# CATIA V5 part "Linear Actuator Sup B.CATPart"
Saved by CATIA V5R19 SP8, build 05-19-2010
Part number: Linear Actuator Sup B
Bounding box of the stored display mesh (mm): x -24.865 to 24.865, y 132.679 to 469.81, z 725.003 to 774.997
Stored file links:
  G:\EU_thinkMotion\CFAO_2010\MMS_groupe3\MMS_groupe3\A reprendre\fovide\fovide\Linear Actuator Sup B.CATPart
  G:\EU_thinkMotion\CFAO_2010\MMS_groupe3\MMS_groupe3\A reprendre\fovide\fovide\fovide.CATProduct
  G:\EU_thinkMotion\CFAO_2010\MMS_groupe3\MMS_groupe3\A reprendre\fovide\fovide\Linear Actuator Sup A 9.CATPart
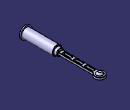
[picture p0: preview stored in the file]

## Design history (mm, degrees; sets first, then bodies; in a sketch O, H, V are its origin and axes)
Parameters
  `longueur poches` = 35 mm
External parameters (linked from other documents)
  `External.Rayon Linear Actuator Sup A` = 30 mm
  `External.Diamètre Linear Actuator Sup A` = 60 mm
Set1
  Plane1: linked copy from another document
  Point1 "Point.B": linked copy from another document
  Line1: linked copy from another document
  Plane2: linked copy from another document
  Line2: linked copy from another document
  DatumCurve1 to DatumCurve3: linked copy from another document
Body1 (main body)
  Sketch1 on Plane1, origin (0, 0, 750), H (1, 0, 0), V (0, 1, 0)
    arc A1 centre (0, 450) radius 20 from (-10, 432.6795) to (10, 432.6795) cw
    point P1 (0, 450)
    point P2 (-10, 432.6795)
    point P3 (10, 432.6795)
    reference projected point E1 (0, 450) from Point1
    point P4 (-10, 432.6795)
    line L1 (10, 432.6795) -> (10, 282.6795)
    line L2 (10, 282.6795) -> (-10, 282.6795)
    line L3 (-10, 282.6795) -> (-10, 432.6795)
    point P5 (10, 432.6795)
    radius A1 = 20
    length L1 = 150
    length L2 = 20 {= `External.Rayon Linear Actuator Sup A` *2/3}
    coincidence: P1 E1, P5 P3, P4 P2
    horizontal: L2 H
    vertical: L1 V, L3 V
  Pad1: profile Sketch1, direction (0, 0, 1), length 5 {= `External.Rayon Linear Actuator Sup A` /6}, mirrored extent
  Sketch2 on Plane2, origin (0, 0, 0), H (0, 1, 0), V (0, 0, 1)
    line L1 (282.6795, 750) -> (282.6795, 765)
    line L2 (282.6795, 765) -> (267.6795, 765)
    line L3 (267.6795, 765) -> (267.6795, 770)
    line L4 (267.6795, 770) -> (137.6795, 770)
    line L5 (137.6795, 770) -> (137.6795, 775)
    line L6 (137.6795, 775) -> (132.6795, 775)
    line L7 (132.6795, 775) -> (132.6795, 750)
    line L8 (132.6795, 750) -> (282.6795, 750)
    reference projected line E1 (282.6795, 745) -> (282.6795, 755) from edge [face of Pad1 from Sketch1.L1 | face of Pad1 from Sketch1.L2]
    reference projected line E2 (450, 750) -> (0, 750) from Line2
    length L6 = 5 {= `External.Rayon Linear Actuator Sup A` /6}
    length L5 = 5 {= `External.Rayon Linear Actuator Sup A` /6}
    length L1 = 15 {= `External.Rayon Linear Actuator Sup A` /2}
    length L2 = 15 {= `External.Rayon Linear Actuator Sup A` /2}
    length L7 = 25 {= `External.Rayon Linear Actuator Sup A` *5/6}
    length L4 = 130
    vertical: L1 V, L3 V, L5 V, L7 V
    horizontal: L2 H, L4 H, L6 H, L8 H
    coincidence: L1 E1, L8 E2
  Shaft1: profile Sketch2, axis Line2, angle 360
  Sketch3 on end face of Pad1, origin (0, 0, 755), H (1, 0, 0), V (0, 1, 0)
    line L1 (-5, 330.1795) -> (5, 330.1795)
    line L2 (5, 330.1795) -> (5, 295.1795)
    line L3 (5, 295.1795) -> (-5, 295.1795)
    line L4 (-5, 295.1795) -> (-5, 330.1795)
    reference projected line E1 (-10, 432.6795) -> (-10, 232.6795) from edge [face of Pad1 from Sketch1.L3 | end face of Pad1]
    reference projected line E2 (15, 282.6795) -> (-15, 282.6795) from edge [face of Shaft1 from Sketch2.L1 | face of Shaft1 from Sketch2.L2]
    length L1 = 10 {= `External.Rayon Linear Actuator Sup A` /3}
    length L2 = 35 {= `longueur poches`}
    distance L4 E1 = 5 {= `External.Rayon Linear Actuator Sup A` /6}
    distance E2 L3 = 12.5
    horizontal: L1 H, L3 H
    vertical: L2 V, L4 V
  Sketch4 on end face of Pad1, origin (0, 0, 755), H (1, 0, 0), V (0, 1, 0)
    line L1 (-5, 377.6795) -> (5, 377.6795)
    line L2 (5, 377.6795) -> (5, 342.6795)
    line L3 (5, 342.6795) -> (-5, 342.6795)
    line L4 (-5, 342.6795) -> (-5, 377.6795)
    reference projected line E1 (-10, 432.6795) -> (-10, 232.6795) from edge [face of Pad1 from Sketch1.L3 | end face of Pad1]
    reference projected line E2 (5, 330.1795) -> (-5, 330.1795) from Sketch3.L1
    length L1 = 10 {= `External.Rayon Linear Actuator Sup A` /3}
    length L2 = 35 {= `longueur poches`}
    distance L4 E1 = 5 {= `External.Rayon Linear Actuator Sup A` /6}
    distance L3 E2 = 12.5
    horizontal: L1 H, L3 H
    vertical: L2 V, L4 V
  Sketch5 on end face of Pad1, origin (0, 0, 755), H (1, 0, 0), V (0, 1, 0)
    line L1 (-5, 425.1795) -> (5, 425.1795)
    line L2 (5, 425.1795) -> (5, 390.1795)
    line L3 (5, 390.1795) -> (-5, 390.1795)
    line L4 (-5, 390.1795) -> (-5, 425.1795)
    reference projected line E1 (-10, 432.6795) -> (-10, 232.6795) from edge [face of Pad1 from Sketch1.L3 | end face of Pad1]
    reference projected line E2 (5, 377.6795) -> (-5, 377.6795) from Sketch4.L1
    length L1 = 10 {= `External.Rayon Linear Actuator Sup A` /3}
    length L2 = 35 {= `longueur poches`}
    distance L4 E1 = 5 {= `External.Rayon Linear Actuator Sup A` /6}
    distance L3 E2 = 12.5
    horizontal: L1 H, L3 H
    vertical: L2 V, L4 V
  Pocket1: profile Sketch5, direction (0, 0, -1), through (limit type 6)
  Pocket2: profile Sketch4, direction (0, 0, -1), through (limit type 6)
  Pocket3: profile Sketch3, direction (0, 0, -1), through (limit type 6)
  Sketch6 on Plane2, origin (0, 0, 0), H (0, 1, 0), V (0, 0, 1)
    line L1 (450, 763) -> (450, 755)
    point P1 (450, 763)
    point P2 (450, 755)
    line L2 (450, 755) -> (463, 755)
    point P3 (463, 755)
    reference projected line E1 (432.6795, 755) -> (470, 755) from edge [face of Pad1 from Sketch1.A1 | end face of Pad1]
    reference projected line E2 (450, 600) -> (450, 900) from Line1
    arc A1 centre (445.5536, 746.7969) radius 19.2787 from (463, 755) to (456, 763) ccw
    point P5 (463, 755)
    point P6 (456, 763)
    line L3 (450, 763) -> (456, 763)
    point P7 (456, 763)
    reference projected line E3 (450, 750) -> (0, 750) from edge of Line2
    point P10 (450, 737)
    point P11 (450, 745)
    point P12 (463, 745)
    point P13 (463, 745)
    point P14 (456, 737)
    point P15 (456, 737)
    line L4 (450, 737) -> (450, 745)
    line L5 (450, 745) -> (463, 745)
    arc A2 centre (445.5536, 753.2031) radius 19.2787 from (463, 745) to (456, 737) cw
    line L6 (450, 737) -> (456, 737)
    length L2 = 13
    length L1 = 8
    radius A1 = 19.2787
    length L3 = 6
    vertical: L1 V
    horizontal: L2 H, L3 H
    coincidence: L2 E1, L1 E2, P5 P3, P7 P6
    symmetry: P1 P10 E3, P2 P11 E3, P3 P12 E3, P5 P13 E3, P6 P14 E3, P7 P15 E3, L1 L4 E3, L2 L5 E3, A1 A2 E3, L3 L6 E3
  Shaft2: profile Sketch6, axis Line1, angle 360
  Fillet1: radius 1, on end face of Pad1; start face of Pad1
  Fillet2: radius 2, on face of Shaft1 from Sketch2.L2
